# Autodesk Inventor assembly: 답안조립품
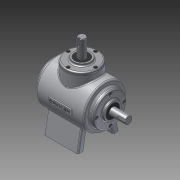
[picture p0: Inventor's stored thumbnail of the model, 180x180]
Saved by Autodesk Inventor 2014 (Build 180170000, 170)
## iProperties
Created: 2015-01
Part Number: 답안조립품
Document SubType Name: Assembly
Designer: basic
Author: basic
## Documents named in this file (15)
- C:\Users\basic\Desktop\450105V1008\450105V1008\답안조립품.iam
- C:\Users\basic\Desktop\450105V1008\450105V1008\본체.ipt
- C:\Users\basic\Desktop\450105V1008\450105V1008\M4.ipt
- C:\Users\basic\Desktop\450105V1008\450105V1008\메인 베벨기어.ipt
- C:\Users\basic\Desktop\450105V1008\450105V1008\메인 축.ipt
- 메인 축.ipt
- C:\Users\basic\Desktop\450105V1008\450105V1008\베어링 6203.ipt
- C:\Users\basic\Desktop\450105V1008\450105V1008\서브 베벨기어.ipt
- C:\Users\basic\Desktop\450105V1008\450105V1008\서브 축.ipt
- 서브 축.ipt
- C:\Users\basic\Desktop\450105V1008\450105V1008\오일실.ipt
- C:\Users\basic\Desktop\450105V1008\450105V1008\커버.ipt
- C:\Users\basic\Desktop\450105V1008\450105V1008\커버2.ipt
- C:\Users\basic\Desktop\450105V1008\450105V1008\키 4x4.ipt
- C:\Users\basic\Desktop\450105V1008\450105V1008\키 5x5.ipt
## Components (12 placed, 1 different names)
1. M4:2 — 각도:1
2. M4:4
3. M4:5
4. M4:6
5. M4:3
6. M4:7 — 각도:2
7. M4:8
8. M4:9
9. M4:1 — 각도:3
10. M4:10
11. M4:11
12. M4:12
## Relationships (3: Angle 3)
- 각도:1 [Angle]: M4:2
- 각도:2 [Angle]: M4:7
- 각도:3 [Angle]: M4:1
